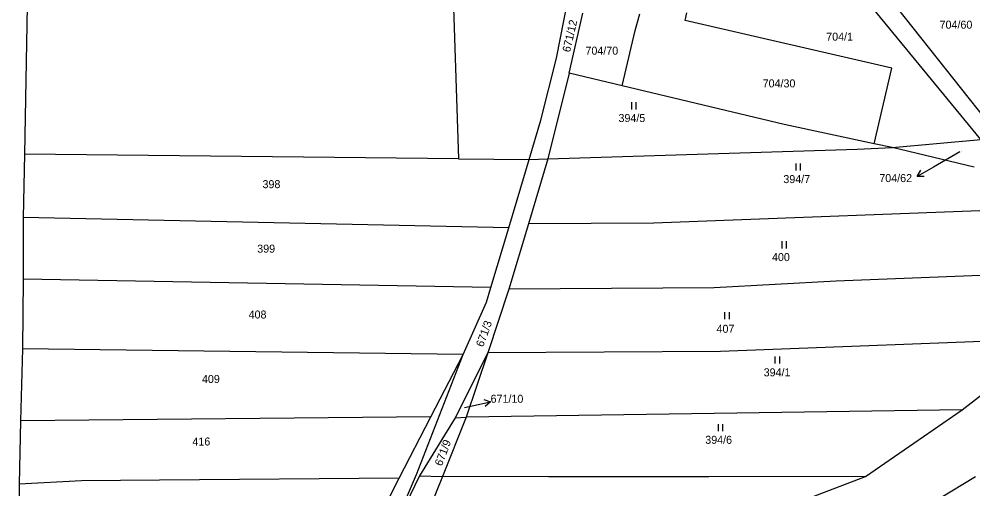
# Model space of a CAD drawing. Extents: x -747333 to -745433, y -1133152 to -1130600.
# Drawn here: x -746396.8 to -746194.2, y -1132600.8 to -1132501 of the extents above; entities that cross this region are included whole.
import ezdxf

# ---------------------------------------------------------------- set-up
doc = ezdxf.new("R2010")
doc.units = 0
for name, color, linetype in [('Vrstva 1', 7, 'Continuous'), ('Vrstva 16', 7, 'Continuous'), ('Vrstva 18', 7, 'Continuous'), ('Vrstva 25', 7, 'Continuous'), ('Vrstva 6', 7, 'Continuous')]:
    doc.layers.add(name, color=color, linetype=linetype)

msp = doc.modelspace()

# ---------------------------------------------------------------- linework, layer by layer
at = {"layer": 'Vrstva 1'}
for p, q in [((-746305.4, -1132474), (-746303.46, -1132530.68)), ((-746303.46, -1132530.68), (-746395.66, -1132529.71)), ((-746303.46, -1132530.68), (-746288.46, -1132530.84)), ((-746288.46, -1132530.84), (-746284.47, -1132530.7))]:
    msp.add_line(p, q, dxfattribs=at)
for points in [[(-746282.68, -1132509.35), (-746280.25, -1132497.07)], [(-746212.16, -1132496.33), (-746191.45, -1132522.4)], [(-746192.5, -1132526.63), (-746215.49, -1132498.68)], [(-746280, -1132512.49), (-746277.07, -1132499.78)], [(-746268.69, -1132515.2), (-746265.92, -1132503.46), (-746264.96, -1132499.91)], [(-746215.21, -1132527.49), (-746211.44, -1132511.42), (-746255.36, -1132501.33), (-746254.97, -1132499.66)], [(-746285.96, -1132522.49), (-746282.68, -1132509.35)], [(-746280, -1132512.49), (-746284.47, -1132530.7)], [(-746268.69, -1132515.2), (-746280, -1132512.49)], [(-746215.21, -1132527.49), (-746234.3, -1132523.43), (-746268.69, -1132515.2)], [(-746288.46, -1132530.84), (-746285.96, -1132522.49)], [(-746211.35, -1132528.31), (-746215.21, -1132527.49)], [(-746193.95, -1132532.5), (-746211.35, -1132528.31)], [(-746292.8, -1132545.37), (-746288.46, -1132530.84)], [(-746284.47, -1132530.7), (-746288.6, -1132544.53)], [(-746296.59, -1132558.03), (-746292.8, -1132545.37)], [(-746288.6, -1132544.53), (-746292.75, -1132558.4)], [(-746297.53, -1132561.17), (-746296.59, -1132558.03)], [(-746292.75, -1132558.4), (-746297.27, -1132571.91)], [(-746302.49, -1132572.23), (-746297.53, -1132561.17)], [(-746297.27, -1132571.91), (-746301.85, -1132585.59)], [(-746312.37, -1132597.72), (-746302.49, -1132572.23)], [(-746196.52, -1132584.02), (-746188.27, -1132577.67)], [(-746217.04, -1132598.15), (-746196.52, -1132584.02)], [(-746301.85, -1132585.59), (-746306.9, -1132598.17)], [(-746318.6, -1132612.27), (-746312.37, -1132597.72)], [(-746306.9, -1132598.17), (-746312.51, -1132612.17)], [(-746253, -1132611.94), (-746217.04, -1132598.15)], [(-746209.12, -1132607.51), (-746193.69, -1132598.19)]]:
    msp.add_lwpolyline(points, dxfattribs=at)
at = {"layer": 'Vrstva 16'}
for p, q in [((-746204.531369, -1132534.441533), (-746206.032192, -1132534.435921)), ((-746298.113598, -1132581.838538), (-746296.683024, -1132582.292364))]:
    msp.add_line(p, q, dxfattribs=at)
for points in [[(-746196.96, -1132529.25), (-746202.56, -1132532.45)], [(-746202.56, -1132532.45), (-746206.032192, -1132534.435921), (-746205.27609, -1132533.139461)], [(-746300.59, -1132583.15), (-746296.683024, -1132582.292364), (-746297.791985, -1132583.303654)], [(-746302.17, -1132583.5), (-746300.59, -1132583.15)]]:
    msp.add_lwpolyline(points, dxfattribs=at)
at = {"layer": 'Vrstva 25'}
for p, q in [((-746266.74, -1132518.69), (-746266.74, -1132520.19)), ((-746265.74, -1132520.19), (-746265.74, -1132518.69)), ((-746231.8, -1132531.66), (-746231.8, -1132533.16)), ((-746230.8, -1132533.16), (-746230.8, -1132531.66)), ((-746234.81, -1132548.22), (-746234.81, -1132549.72)), ((-746233.81, -1132549.72), (-746233.81, -1132548.22)), ((-746246.94, -1132563.27), (-746246.94, -1132564.77)), ((-746245.94, -1132564.77), (-746245.94, -1132563.27)), ((-746236.25, -1132572.7), (-746236.25, -1132574.2)), ((-746235.25, -1132574.2), (-746235.25, -1132572.7)), ((-746248.35, -1132587.03), (-746248.35, -1132588.53)), ((-746247.35, -1132588.53), (-746247.35, -1132587.03))]:
    msp.add_line(p, q, dxfattribs=at)
at = {"layer": 'Vrstva 6'}
for points in [[(-746394.67, -1132474.61), (-746395.66, -1132529.71)], [(-746211.35, -1132528.31), (-746192.5, -1132526.63)], [(-746284.47, -1132530.7), (-746218.78, -1132528.63)], [(-746218.78, -1132528.63), (-746211.35, -1132528.31)], [(-746395.66, -1132529.71), (-746395.95, -1132543.13)], [(-746179.61, -1132541.25), (-746261.95, -1132544.34)], [(-746395.95, -1132543.13), (-746395.95, -1132556.26)], [(-746292.8, -1132545.37), (-746395.95, -1132543.13)], [(-746261.95, -1132544.34), (-746288.6, -1132544.53)], [(-746170.9, -1132554.64), (-746223.27, -1132556.71)], [(-746395.95, -1132556.26), (-746396.11, -1132571.09)], [(-746296.59, -1132558.03), (-746395.95, -1132556.26)], [(-746223.27, -1132556.71), (-746249.19, -1132558.09)], [(-746249.19, -1132558.09), (-746292.75, -1132558.4)], [(-746177.34, -1132568.9), (-746247.81, -1132571.64)], [(-746396.11, -1132571.09), (-746396.53, -1132586.37)], [(-746302.49, -1132572.23), (-746396.11, -1132571.09)], [(-746297.27, -1132571.91), (-746304.21, -1132585.68)], [(-746247.81, -1132571.64), (-746297.27, -1132571.91)], [(-746309.34, -1132585.51), (-746302.49, -1132572.23)], [(-746196.52, -1132584.02), (-746301.85, -1132585.59)], [(-746396.53, -1132586.37), (-746396.82, -1132599.79)], [(-746309.34, -1132585.51), (-746396.53, -1132586.37)], [(-746316.05, -1132598.5), (-746309.34, -1132585.51)], [(-746304.21, -1132585.68), (-746311.75, -1132598.02)], [(-746304.21, -1132585.68), (-746301.85, -1132585.59)], [(-746316.05, -1132598.5), (-746367, -1132598.93)], [(-746322.47, -1132611.21), (-746316.05, -1132598.5)], [(-746311.75, -1132598.02), (-746318.6, -1132612.27)], [(-746311.75, -1132598.02), (-746306.9, -1132598.17)], [(-746284.39, -1132598.26), (-746306.9, -1132598.17)], [(-746250.33, -1132598.26), (-746284.39, -1132598.26)], [(-746217.04, -1132598.15), (-746250.33, -1132598.26)], [(-746383.55, -1132599.07), (-746396.82, -1132599.79)], [(-746396.82, -1132599.79), (-746396.82, -1132612.92)], [(-746367, -1132598.93), (-746383.55, -1132599.07)]]:
    msp.add_lwpolyline(points, dxfattribs=at)

# ---------------------------------------------------------------- texts
at = {"layer": 'Vrstva 16'}
for s, p in [('704/62', (-746214.084438, -1132535.64)), ('671/10', (-746296.66, -1132582.51))]:
    msp.add_text(s, height=1.7, dxfattribs=at).set_placement(p)
at = {"layer": 'Vrstva 18'}
for s, rotation, p in [('671/12', 77.01858, (-746279.79294, -1132508.166174)), ('671/3', 70.18317, (-746298.24, -1132570.79)), ('671/9', 69.40395, (-746307.01, -1132596.08))]:
    msp.add_text(s, height=1.7, rotation=rotation, dxfattribs=at).set_placement(p)
for s, height, p in [('704/60', 1.7, (-746201.28, -1132503.06)), ('704/1', 1.7, (-746225.365006, -1132505.6)), ('704/70', 1.7, (-746276.505931, -1132508.58)), ('704/30', 1.7, (-746238.865931, -1132515.53)), ('394/5', 1.7, (-746269.49, -1132522.89)), ('704/62', 0.1, (-746196.96, -1132529.25)), ('398', 1.7, (-746345.11, -1132536.93)), ('394/7', 1.7, (-746234.47, -1132535.86)), ('399', 1.7, (-746346.23, -1132550.63)), ('400', 1.7, (-746236.88, -1132552.42)), ('408', 1.7, (-746348.06, -1132564.62)), ('407', 1.7, (-746248.66, -1132567.65)), ('394/1', 1.7, (-746238.65, -1132576.9)), ('409', 1.7, (-746357.97, -1132578.31)), ('671/10', 0.1, (-746302.17, -1132583.5)), ('416', 1.7, (-746360, -1132591.59)), ('394/6', 1.7, (-746251.06, -1132591.23))]:
    msp.add_text(s, height=height, dxfattribs=at).set_placement(p)

doc.saveas('drawing.dxf')
